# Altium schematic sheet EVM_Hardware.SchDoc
size 431 x 279 mm; Date: Not shown in title block; ApprovedBy: Not shown in title block; CheckedBy: Not shown in title block; Author: Not shown in title block; CompanyName: Not shown in title block; Engineer: Not shown in title block; Organization: Not shown in title block; Address1: Not shown in title block; Address2: Not shown in title block; Address3: Not shown in title block; Address4: Not shown in title block; DocumentNumber: 1; Revision: Use project parameter SCH_Rev; SheetNumber: 3; SheetTotal: 3; PageSetup: Record=PageOptions¦CenterHorizontal=True¦CenterVertical=True¦PrintScale=1.00¦XCorrection=1.00¦YCorrection=1.00¦PrintKind=0¦BorderSize=5000000¦LeftOffset=0¦BottomOffset=0¦Orientation=2¦PaperLength=1000¦PaperWidth=1000¦Scale=100¦PaperSource=15¦PrintQuality=600¦MediaType=1¦DitherType=10¦PaperKind=Letter¦PrintScaleMode=1
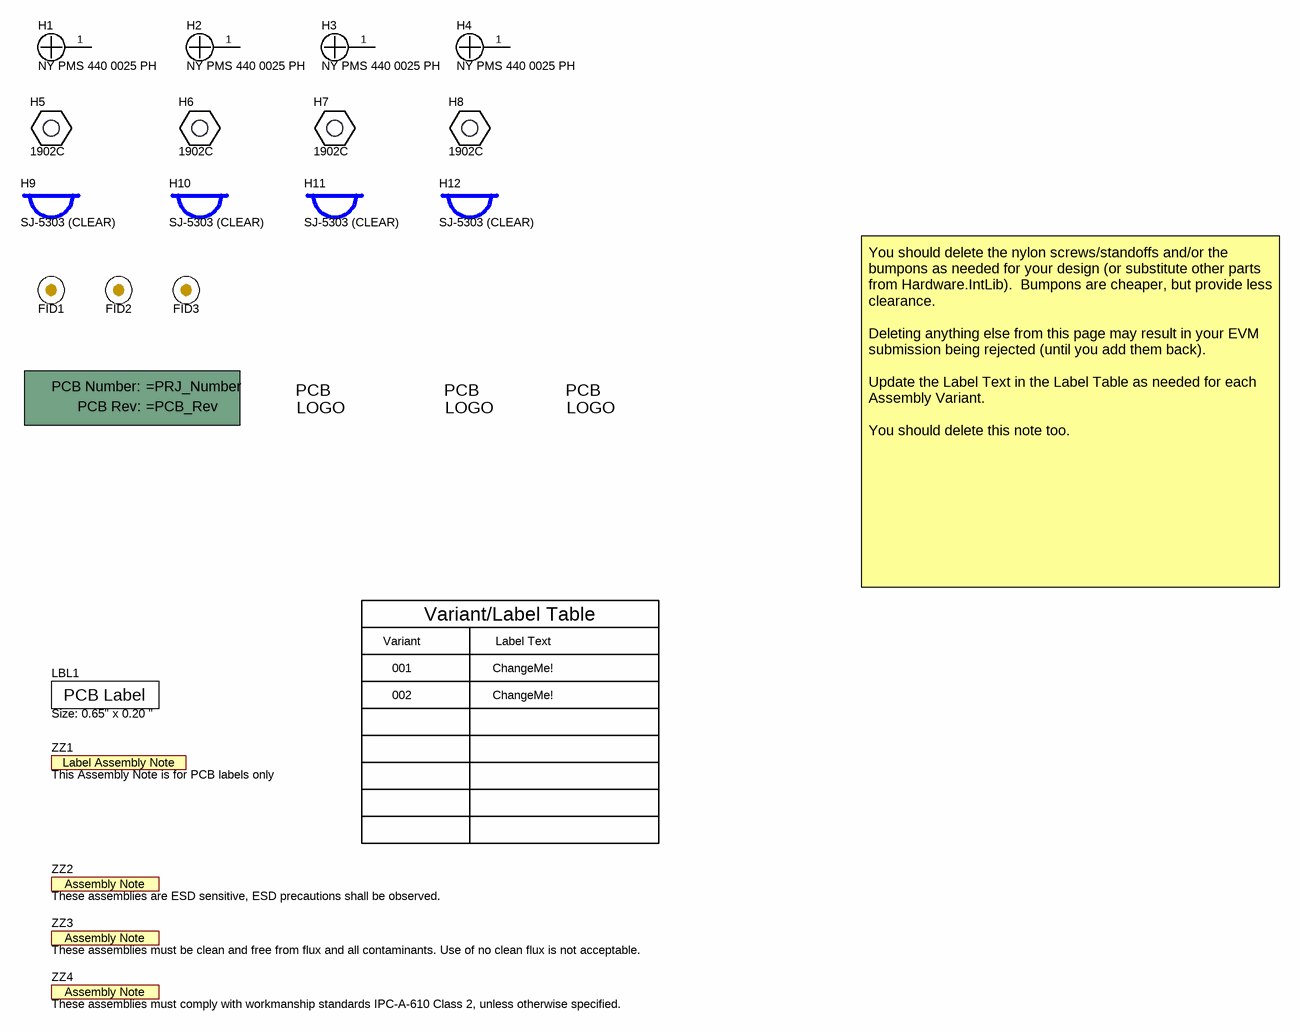
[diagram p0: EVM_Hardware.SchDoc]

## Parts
!PCB  Printed Circuit Board  (value not drawn)  (mechanical)
FID1  Fiducial  [Fiducial10-20]  (value not drawn)
FID2  Fiducial  [Fiducial10-20]  (value not drawn)
FID3  Fiducial  [Fiducial10-20]  (value not drawn)
H1  NY PMS 440 0025 PH  [NY PMS 440 0025 PH]
H2  NY PMS 440 0025 PH  [NY PMS 440 0025 PH]
H3  NY PMS 440 0025 PH  [NY PMS 440 0025 PH]
H4  NY PMS 440 0025 PH  [NY PMS 440 0025 PH]
H5  1902C  [Keystone_1902C]
H6  1902C  [Keystone_1902C]
H7  1902C  [Keystone_1902C]
H8  1902C  [Keystone_1902C]
H9  SJ-5303 (CLEAR)  [Bumpon_SJ5003Transparent]
H10  SJ-5303 (CLEAR)  [Bumpon_SJ5003Transparent]
H11  SJ-5303 (CLEAR)  [Bumpon_SJ5003Transparent]
H12  SJ-5303 (CLEAR)  [Bumpon_SJ5003Transparent]
LBL1  Size: 0.65" x 0.20 "  [Label_650x200]
Logo1  Texas Instruments  [TI_Stacked_Overlay_Small]  (value not drawn)  (no BOM)
Logo2  Pb-Free Symbol  [Pb-Free_Overlay_Small]  (value not drawn)  (no BOM)
Logo3  FCC disclaimer  [FCC_disclaimer]  (value not drawn)  (no BOM)
ZZ1  This Assembly Note is for PCB labels only  [AssemblyNoteLabel]  (no BOM)
ZZ2  These assemblies are ESD sensitive, ESD precautions shall be observed.  [AssemblyNote]  (no BOM)
ZZ3  These assemblies must be clean and free from flux and all contaminants. Use of no clean flux is not acceptable.  [AssemblyNote]  (no BOM)
ZZ4  These assemblies must comply with workmanship standards IPC-A-610 Class 2, unless otherwise specified.  [AssemblyNote]  (no BOM)

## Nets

Not connected (* = marked no-connect by the designer): H1 1; H2 1; H3 1; H4 1

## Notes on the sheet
- Variant
- Variant/Label Table
- Label Text
- You should delete the nylon screws/standoffs and/or the bumpons as needed for your design (or substitute other parts from Hardware.IntLib).  Bumpons are cheaper, but provide less clearance.
  Deleting anything else from this page may result in your EVM submission being rejected (until you add them back).
  Update the Label Text in the Label Table as needed for each Assembly Variant.
  You should delete this note too.
- 001
- 002
- ChangeMe!

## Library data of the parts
!PCB = PCB: Manufacturer: Any; SymbolCreator: a0412235
FID1-FID3 = Fiducial: Fiducial mark.  There is nothing to buy or mount.; SymbolCreator: codlsc
H1-H4 = NY PMS 440 0025 PH: Machine Screw, Round, #4-40 x 1/4, Nylon, Philips panhead; Manufacturer: B&F Fastener Supply; CompType: Hardware; SymbolCreator: codlsc; U/M: EA; Green_Lifecycle: Not Set; Green_REACh: Incomplete
H5-H8 = 1902C: Standoff, Hex, 0.5"L #4-40 Nylon; Manufacturer: Keystone; Green_Lifecycle: Active; Green_REACh: Passed; SymbolCreator: a0412235
H9-H12 = SJ-5303 (CLEAR): Bumpon, Hemisphere, 0.44 X 0.20, Clear; Manufacturer: 3M; SymbolCreator: a0412235; Green_Lifecycle: Active; Green_REACh: Passed
LBL1 = THT-14-423-10: Thermal Transfer Printable Labels, 0.650" W x 0.200" H - 10,000 per roll; Manufacturer: Brady; SymbolCreator: a0412235; CompType: Label; Green_Lifecycle: Not Set; Green_REACh: Incomplete
Logo1 = TI_Logo: Texas Instrument Corporate Signature; SymbolCreator: a0412235
Logo2 = Pb-Free: SymbolCreator: a0412235
Logo3 = FCC_disclaimer: SymbolCreator: a0412235
ZZ1 = AssemblyNoteLabel: SymbolCreator: a0412235
ZZ2-ZZ4 = AssemblyNote: SymbolCreator: codlsc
